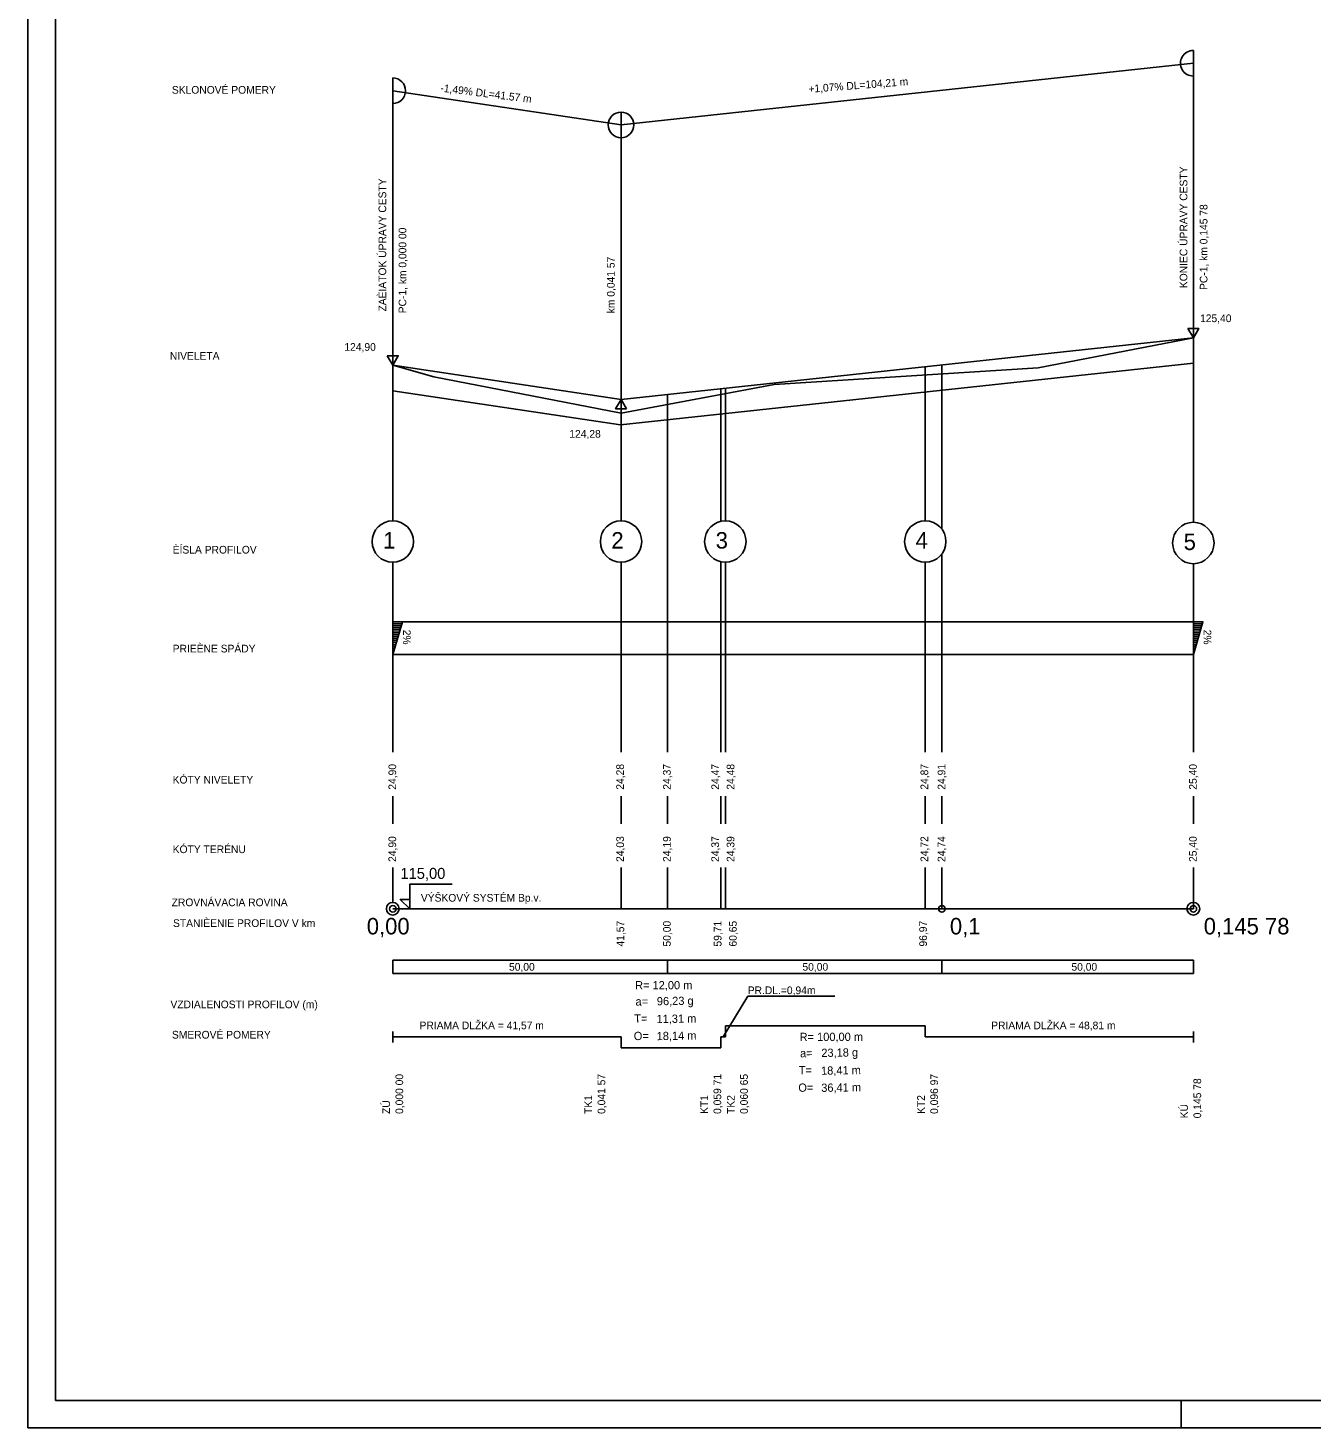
# Model space of a CAD drawing. Extents: x -498883 to -498457, y -1280289 to -1279879.
# Drawn here: x -498883.4 to -498649.6, y -1280289.4 to -1280034.4 of the extents above; entities that cross this region are included whole.
import ezdxf

# ---------------------------------------------------------------- set-up
doc = ezdxf.new("R2010")
doc.units = 0
for name, color, linetype in [('Vrstva 1', 7, 'Continuous'), ('Vrstva 11', 7, 'Continuous'), ('Vrstva 12', 7, 'Continuous'), ('Vrstva 13', 7, 'Continuous'), ('Vrstva 4', 7, 'Continuous'), ('Vrstva 5', 7, 'Continuous'), ('Vrstva 8', 7, 'Continuous')]:
    doc.layers.add(name, color=color, linetype=linetype)

# ---------------------------------------------------------------- blocks, each defined once
blk = doc.blocks.new('SC98140')
at = {"layer": 'Vrstva 1'}
blk.add_line((0, 0), (0, 0), dxfattribs=at)

msp = doc.modelspace()

# ---------------------------------------------------------------- linework, layer by layer
at = {"layer": 'Vrstva 1'}
for p, q in [((-498883.41, -1279879.38), (-498883.41, -1280289.38)), ((-498878.41, -1279884.38), (-498878.41, -1280284.38)), ((-498883.41, -1280284.38), (-498883.41, -1280289.38)), ((-498878.41, -1280284.38), (-498468.41, -1280284.38)), ((-498673.41, -1280284.38), (-498673.41, -1280289.38)), ((-498883.41, -1280289.38), (-498463.41, -1280289.38))]:
    msp.add_line(p, q, dxfattribs=at)
at = {"layer": 'Vrstva 11'}
for p, q in [((-498775.42, -1280102.03), (-498671.21, -1280090.81)), ((-498816.99, -1280095.81), (-498775.42, -1280102.03)), ((-498815.24, -1280142.52), (-498816.99, -1280142.52)), ((-498669.46, -1280142.52), (-498671.21, -1280142.52)), ((-498815.35, -1280142.9), (-498816.99, -1280142.9)), ((-498815.46, -1280143.27), (-498816.99, -1280143.27)), ((-498815.57, -1280143.65), (-498816.99, -1280143.65)), ((-498815.68, -1280144.02), (-498816.99, -1280144.02)), ((-498815.79, -1280144.4), (-498816.99, -1280144.4)), ((-498815.9, -1280144.77), (-498816.99, -1280144.77)), ((-498816, -1280145.15), (-498816.99, -1280145.15)), ((-498669.57, -1280142.9), (-498671.21, -1280142.9)), ((-498669.68, -1280143.27), (-498671.21, -1280143.27)), ((-498669.79, -1280143.65), (-498671.21, -1280143.65)), ((-498669.9, -1280144.02), (-498671.21, -1280144.02)), ((-498670.01, -1280144.4), (-498671.21, -1280144.4)), ((-498670.12, -1280144.77), (-498671.21, -1280144.77)), ((-498670.22, -1280145.15), (-498671.21, -1280145.15)), ((-498816.11, -1280145.52), (-498816.99, -1280145.52)), ((-498816.22, -1280145.9), (-498816.99, -1280145.9)), ((-498816.33, -1280146.27), (-498816.99, -1280146.27)), ((-498816.44, -1280146.65), (-498816.99, -1280146.65)), ((-498816.55, -1280147.02), (-498816.99, -1280147.02)), ((-498816.66, -1280147.4), (-498816.99, -1280147.4)), ((-498816.77, -1280147.77), (-498816.99, -1280147.77)), ((-498670.33, -1280145.52), (-498671.21, -1280145.52)), ((-498670.44, -1280145.9), (-498671.21, -1280145.9)), ((-498670.55, -1280146.27), (-498671.21, -1280146.27)), ((-498670.66, -1280146.65), (-498671.21, -1280146.65)), ((-498670.77, -1280147.02), (-498671.21, -1280147.02)), ((-498670.88, -1280147.4), (-498671.21, -1280147.4)), ((-498670.99, -1280147.77), (-498671.21, -1280147.77)), ((-498816.88, -1280148.15), (-498816.99, -1280148.15)), ((-498671.1, -1280148.15), (-498671.21, -1280148.15)), ((-498815.83, -1280194.81), (-498671.21, -1280194.81)), ((-498766.99, -1280204.17), (-498766.99, -1280206.57)), ((-498716.99, -1280204.17), (-498716.99, -1280206.57)), ((-498671.21, -1280204.17), (-498671.21, -1280206.57)), ((-498752.31, -1280210.7), (-498756.85, -1280218.15)), ((-498752.31, -1280210.7), (-498736.47, -1280210.7))]:
    msp.add_line(p, q, dxfattribs=at)
for points in [[(-498816.99, -1280142.52), (-498816.99, -1280148.52), (-498815.24, -1280142.52), (-498816.99, -1280142.52)], [(-498671.21, -1280142.52), (-498671.21, -1280148.52), (-498669.46, -1280142.52), (-498671.21, -1280142.52)]]:
    msp.add_lwpolyline(points, dxfattribs=at)
for centre in [(-498816.99, -1280127.92), (-498775.42, -1280127.92), (-498756.43, -1280127.92), (-498720.02, -1280127.92), (-498671.21, -1280128.19)]:
    msp.add_circle(centre, 3.77, dxfattribs=at)
at = {"layer": 'Vrstva 13'}
for p, q in [((-498671.21, -1280124.42), (-498671.21, -1280038.48)), ((-498775.42, -1280052.03), (-498671.21, -1280040.81)), ((-498816.99, -1280124.15), (-498816.99, -1280043.48)), ((-498816.99, -1280045.81), (-498775.42, -1280052.03)), ((-498775.42, -1280049.71), (-498775.42, -1280124.15)), ((-498699.49, -1280096.31), (-498671.21, -1280090.81)), ((-498816.99, -1280095.81), (-498809.49, -1280097.91)), ((-498747.56, -1280099.31), (-498699.49, -1280096.31)), ((-498720.02, -1280096.07), (-498720.02, -1280124.15)), ((-498716.99, -1280124.15), (-498716.99, -1280095.74)), ((-498809.49, -1280097.91), (-498775.42, -1280104.51)), ((-498775.42, -1280104.51), (-498747.56, -1280099.31)), ((-498766.99, -1280131.68), (-498766.99, -1280101.13)), ((-498757.28, -1280100.08), (-498757.28, -1280124.25)), ((-498756.43, -1280099.99), (-498756.43, -1280124.15)), ((-498716.99, -1280125.68), (-498716.99, -1280124.15)), ((-498816.99, -1280166.31), (-498816.99, -1280131.68)), ((-498775.42, -1280131.68), (-498775.42, -1280166.31)), ((-498766.99, -1280166.31), (-498766.99, -1280131.68)), ((-498757.28, -1280131.58), (-498757.28, -1280166.31)), ((-498756.43, -1280131.68), (-498756.43, -1280166.31)), ((-498720.02, -1280131.68), (-498720.02, -1280166.31)), ((-498716.99, -1280166.31), (-498716.99, -1280130.15)), ((-498671.21, -1280166.31), (-498671.21, -1280131.95)), ((-498816.99, -1280142.52), (-498671.21, -1280142.52)), ((-498816.99, -1280148.52), (-498671.21, -1280148.52)), ((-498816.99, -1280179.31), (-498816.99, -1280174.31)), ((-498775.42, -1280174.31), (-498775.42, -1280179.31)), ((-498766.99, -1280179.31), (-498766.99, -1280174.31)), ((-498757.28, -1280174.31), (-498757.28, -1280179.31)), ((-498756.43, -1280174.31), (-498756.43, -1280179.31)), ((-498720.02, -1280174.31), (-498720.02, -1280179.31)), ((-498716.99, -1280179.31), (-498716.99, -1280174.31)), ((-498671.21, -1280179.31), (-498671.21, -1280174.31)), ((-498816.99, -1280193.65), (-498816.99, -1280187.31)), ((-498775.42, -1280187.31), (-498775.42, -1280194.81)), ((-498766.99, -1280194.81), (-498766.99, -1280187.31)), ((-498757.28, -1280187.31), (-498757.28, -1280194.81)), ((-498756.43, -1280187.31), (-498756.43, -1280194.81)), ((-498720.02, -1280187.31), (-498720.02, -1280194.81)), ((-498716.99, -1280194.81), (-498716.99, -1280187.31)), ((-498671.21, -1280194.81), (-498671.21, -1280187.31)), ((-498815.83, -1280194.81), (-498717.58, -1280194.81))]:
    msp.add_line(p, q, dxfattribs=at)
for points in [[(-498672.2, -1280089.09), (-498671.21, -1280090.81), (-498670.22, -1280089.09), (-498672.2, -1280089.09)], [(-498817.98, -1280094.09), (-498816.99, -1280095.81), (-498816, -1280094.09), (-498817.98, -1280094.09)], [(-498774.43, -1280103.75), (-498775.42, -1280102.03), (-498776.41, -1280103.75), (-498774.43, -1280103.75)], [(-498813.85, -1280193.11), (-498815.62, -1280193.11), (-498813.85, -1280194.81), (-498813.85, -1280190.3), (-498806.16, -1280190.3)]]:
    msp.add_lwpolyline(points, dxfattribs=at)
for centre, radius in [((-498775.42, -1280052.03), 2.33), ((-498816.99, -1280194.81), 1.16), ((-498671.21, -1280194.81), 1.16), ((-498816.99, -1280194.81), 0.592), ((-498716.99, -1280194.81), 0.592), ((-498671.21, -1280194.81), 0.592)]:
    msp.add_circle(centre, radius, dxfattribs=at)
for centre, start, end in [((-498671.21, -1280040.81), 89.9981, 270.0019), ((-498816.99, -1280045.81), 270, 90)]:
    msp.add_arc(centre, 2.33, start, end, dxfattribs=at)
at = {"layer": 'Vrstva 8'}
for p, q in [((-498775.51, -1280106.67), (-498671.21, -1280095.44)), ((-498816.99, -1280100.46), (-498775.51, -1280106.67)), ((-498816.99, -1280194.81), (-498671.21, -1280194.81)), ((-498816.99, -1280204.17), (-498671.21, -1280204.17)), ((-498816.99, -1280204.17), (-498816.99, -1280206.57)), ((-498816.99, -1280206.57), (-498671.21, -1280206.57)), ((-498756.43, -1280216.15), (-498720.02, -1280216.15)), ((-498756.43, -1280218.15), (-498756.43, -1280216.15)), ((-498720.02, -1280218.15), (-498720.02, -1280216.15)), ((-498816.99, -1280219.15), (-498816.99, -1280217.15)), ((-498816.99, -1280218.15), (-498775.42, -1280218.15)), ((-498775.42, -1280218.15), (-498775.42, -1280220.15)), ((-498757.28, -1280218.15), (-498756.43, -1280218.15)), ((-498757.28, -1280218.15), (-498757.28, -1280220.15)), ((-498720.02, -1280218.15), (-498671.21, -1280218.15)), ((-498671.21, -1280219.15), (-498671.21, -1280217.15)), ((-498775.42, -1280220.15), (-498757.28, -1280220.15))]:
    msp.add_line(p, q, dxfattribs=at)

# ---------------------------------------------------------------- block references
at = {"layer": 'Vrstva 11'}
for p in [(-498671.21, -1280090.81), (-498816.99, -1280095.81)]:
    msp.add_blockref('SC98140', p, dxfattribs=at)
at = {"layer": 'Vrstva 11', "rotation": 180}
msp.add_blockref('SC98140', (-498775.42, -1280102.03), dxfattribs=at)

# ---------------------------------------------------------------- texts
at = {"layer": 'Vrstva 12'}
for s, rotation, p in [('KONIEC ÚPRAVY CESTY', 90, (-498672.3, -1280081.77)), ('ZAÈIATOK ÚPRAVY CESTY', 90, (-498818.18, -1280086.02)), ('PC-1, km 0,145 78', 90, (-498668.64, -1280082.1)), ('PC-1, km 0,000 00', 90, (-498814.52, -1280086.35)), ('km 0,041 57', 90, (-498776.58, -1280086.35)), ('2%', 270, (-498815.12, -1280143.98)), ('2%', 270, (-498669.34, -1280143.98)), ('24,90', 90, (-498816.37, -1280173.12)), ('24,28', 90, (-498774.89, -1280173.12)), ('24,37', 90, (-498766.37, -1280173.12)), ('24,47', 90, (-498757.58, -1280173.12)), ('24,48', 90, (-498754.78, -1280173.12)), ('24,87', 90, (-498719.49, -1280173.12)), ('24,91', 90, (-498716.37, -1280173.12)), ('25,40', 90, (-498670.59, -1280173.12)), ('24,90', 90, (-498816.37, -1280186.28)), ('24,03', 90, (-498774.89, -1280186.28)), ('24,19', 90, (-498766.37, -1280186.28)), ('24,37', 90, (-498757.58, -1280186.28)), ('24,39', 90, (-498754.78, -1280186.28)), ('24,72', 90, (-498719.49, -1280186.28)), ('24,74', 90, (-498716.37, -1280186.28)), ('25,40', 90, (-498670.59, -1280186.28)), ('41,57', 90, (-498774.84, -1280201.69)), ('50,00', 90, (-498766.37, -1280201.69)), ('59,71', 90, (-498757.13, -1280201.69)), ('60,65', 90, (-498754.36, -1280201.69)), ('96,97', 90, (-498719.72, -1280201.69)), ('0,000 00', 90, (-498815.09, -1280232.18)), ('0,041 57', 90, (-498778.29, -1280232.18)), ('0,059 71', 90, (-498757.18, -1280232.18)), ('0,060 65', 90, (-498752.33, -1280232.18)), ('0,096 97', 90, (-498717.7, -1280232.18)), ('0,145 78', 90, (-498669.79, -1280232.98)), ('TK1', 90, (-498780.69, -1280232.18)), ('KT1', 90, (-498759.58, -1280232.18)), ('TK2', 90, (-498754.73, -1280232.18)), ('KT2', 90, (-498720.1, -1280232.18)), ('ZÚ', 90, (-498817.49, -1280232.18)), ('KÚ', 90, (-498672.19, -1280232.98))]:
    msp.add_text(s, height=1.4, rotation=rotation, dxfattribs=at).set_placement(p)
for s, height, p in [('125,40', 1.4, (-498669.99, -1280087.96)), ('124,90', 1.4, (-498825.8, -1280093.18)), ('124,28', 1.4, (-498784.84, -1280109.01)), ('1', 3, (-498818.75, -1280129.2)), ('2', 3, (-498777.18, -1280129.2)), ('3', 3, (-498758.19, -1280129.2)), ('4', 3, (-498721.78, -1280129.2)), ('5', 3, (-498672.97, -1280129.47)), ('KÓTY TERÉNU', 1.4, (-498857.06, -1280184.67)), ('115,00', 2, (-498815.59, -1280189.37)), ('VÝŠKOVÝ SYSTÉM Bp.v.', 1.4, (-498811.87, -1280193.51)), ('0,00', 3, (-498821.72, -1280199.48)), ('0,1', 3, (-498715.54, -1280199.48)), ('0,145 78', 3, (-498669.32, -1280199.48)), ('50,00', 1.4, (-498795.82, -1280206.09)), ('50,00', 1.4, (-498742.39, -1280206.09)), ('50,00', 1.4, (-498693.41, -1280206.09)), ('PR.DL.=0,94m', 1.4, (-498752.35, -1280210.36)), ('PRIAMA DLŽKA = 41,57 m', 1.4, (-498812.11, -1280216.76)), ('PRIAMA DLŽKA = 48,81 m', 1.4, (-498708.02, -1280216.76))]:
    msp.add_text(s, height=height, dxfattribs=at).set_placement(p)
at = {"layer": 'Vrstva 4'}
for s, p in [('SKLONOVÉ POMERY', (-498857.21, -1280046.35)), ('NIVELETA', (-498857.58, -1280094.8)), ('ÈÍSLA PROFILOV', (-498857.06, -1280130.11)), ('PRIEÈNE SPÁDY', (-498857.06, -1280148.12)), ('KÓTY NIVELETY', (-498857.06, -1280172)), ('ZROVNÁVACIA ROVINA', (-498857.25, -1280194.34)), ('STANIÈENIE PROFILOV V km', (-498857, -1280198.13)), ('VZDIALENOSTI PROFILOV (m)', (-498857.47, -1280212.93)), ('SMEROVÉ POMERY', (-498857.2, -1280218.45))]:
    msp.add_text(s, height=1.4, dxfattribs=at).set_placement(p)
for s, rotation, p in [('-1,49% DL=41.57 m', 352.8639, (-498808.37, -1280045.96)), ('+1,07% DL=104,21 m', 4.4159, (-498741.25, -1280046.2))]:
    msp.add_text(s, height=1.4, rotation=rotation, dxfattribs=at).set_placement(p)
at = {"layer": 'Vrstva 5'}
for s, rotation, p in [('R= 12,00 m', 0.1235, (-498772.86, -1280209.49)), ('a=', 0.9266, (-498772.77, -1280212.45)), ('96,23 g', 0.9266, (-498768.89, -1280212.4)), ('T=', 0.9266, (-498773, -1280215.56)), ('11,31 m', 0.9266, (-498768.95, -1280215.64)), ('O=', 0.9266, (-498773.09, -1280218.74)), ('18,14 m', 0.9266, (-498768.92, -1280218.75)), ('R= 100,00 m', 0.1235, (-498742.9, -1280218.9)), ('a=', 0.9266, (-498742.81, -1280221.87)), ('23,18 g', 0.9266, (-498738.94, -1280221.81)), ('T=', 0.9266, (-498743.04, -1280224.98)), ('18,41 m', 0.9266, (-498738.99, -1280225.05)), ('O=', 0.9266, (-498743.13, -1280228.15)), ('36,41 m', 0.9266, (-498738.96, -1280228.17))]:
    msp.add_text(s, height=1.5, rotation=rotation, dxfattribs=at).set_placement(p)

doc.saveas('drawing.dxf')
